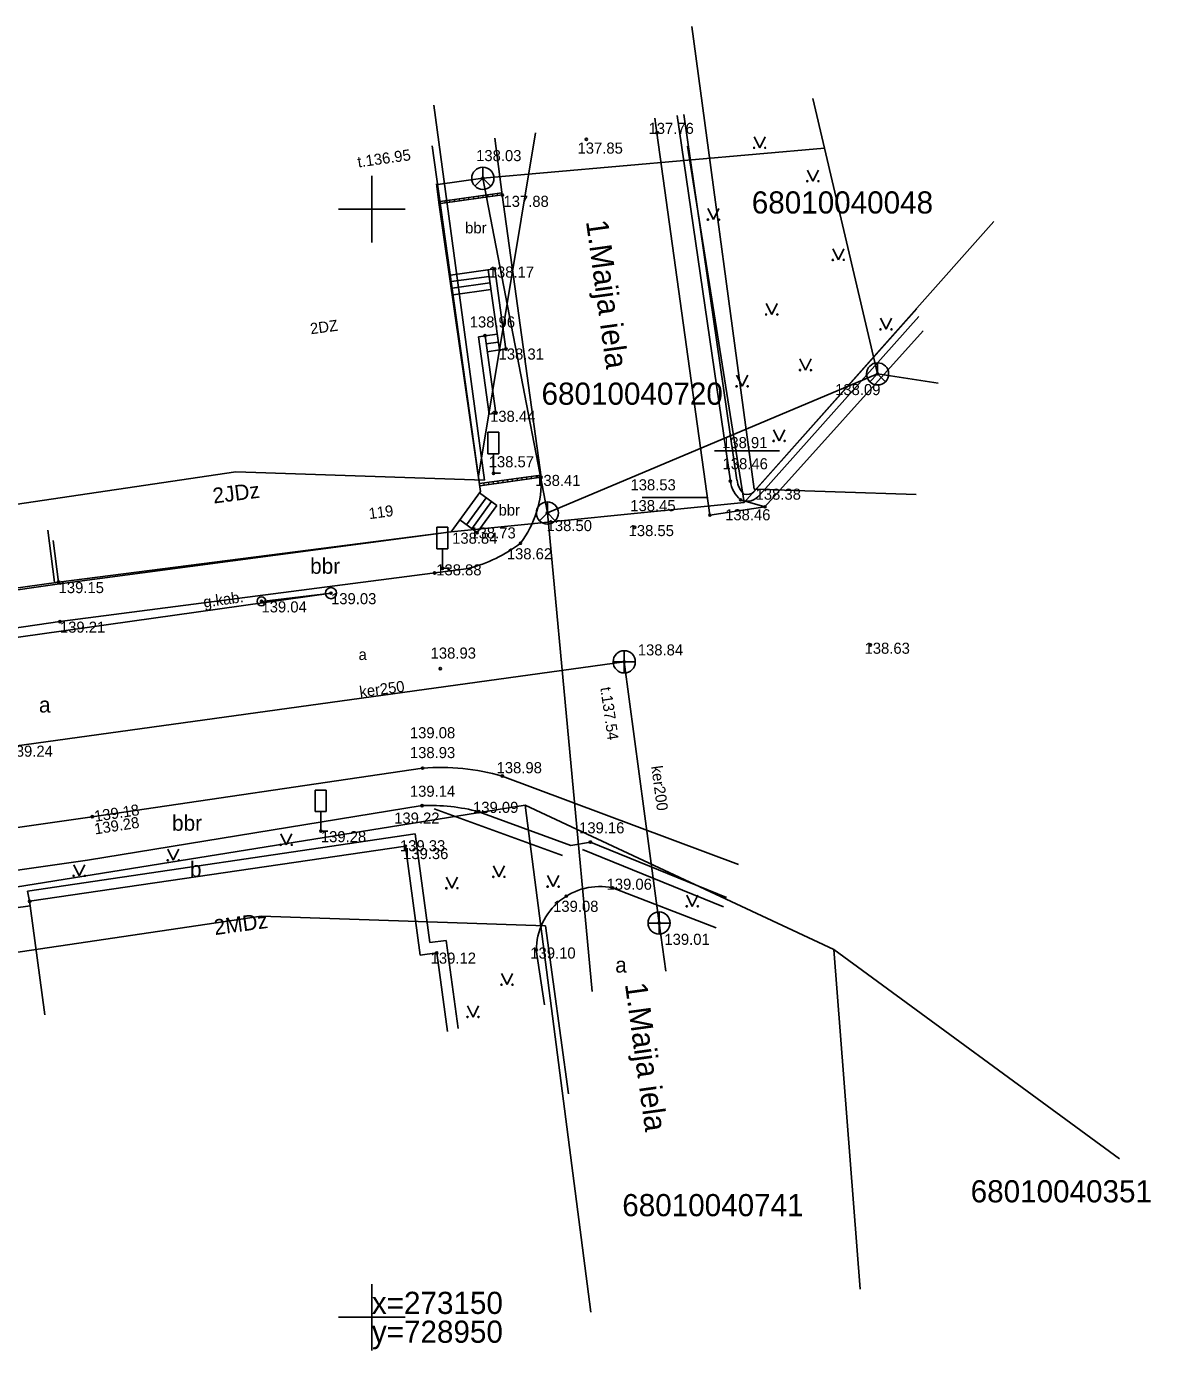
# Model space of a CAD drawing. Extents: x 728785 to 728985, y 273137 to 273208.
# Drawn here: x 728934.4 to 728985.1, y 273148.5 to 273208.2 of the extents above; entities that cross this region are included whole.
import ezdxf

# ---------------------------------------------------------------- set-up
doc = ezdxf.new("R2010")
doc.units = 0
for name, color, linetype in [('APGR_SARK_####_####_#', 7, 'Continuous'), ('BUVE_BDET_####_####_#', 7, 'Continuous'), ('BUVE_EKAS_####_####_#', 7, 'Continuous'), ('BUVE_EKAS_ADRS_TKST_#', 7, 'Continuous'), ('BUVE_EKAS_RAKS_TKST_#', 7, 'Continuous'), ('CELI_CAPM_####_####_#', 7, 'Continuous'), ('CELI_CMAL_####_####_#', 7, 'Continuous'), ('CELI_CSEG_####_TKST_#', 7, 'Continuous'), ('CELI_ELEM_####_####_#', 7, 'Continuous'), ('CELI_IELA_####_TKST_#', 7, 'Continuous'), ('ELEK_ELEM_####_####_#', 7, 'Continuous'), ('ELEK_STUT_####_####_#', 7, 'Continuous'), ('ELEK_VADV_ZSPR_####_#', 7, 'Continuous'), ('ELEK_VADV_ZSPR_TKST_#', 7, 'Continuous'), ('GEOD_ELEM_####_####_#', 7, 'Continuous'), ('GEOD_KORD_####_TKST_#', 7, 'Continuous'), ('RELJ_AATZ_####_TKST_#', 7, 'Continuous'), ('RELJ_ELEM_####_####_#', 7, 'Continuous'), ('ROBZ_KADS_####_TKST_#', 7, 'Continuous'), ('ROBZ_UZMR_####_####_#', 7, 'Continuous'), ('SAKK_ELEM_####_####_#', 7, 'Continuous'), ('SAKK_ELEM_####_TKST_#', 7, 'Continuous'), ('SAKK_KKAN_####_####_#', 7, 'Continuous'), ('SAKT_VADV_PKAB_####_#', 7, 'Continuous'), ('SKAN_ELEM_####_####_#', 7, 'Continuous'), ('SKAN_ELEM_PAST_TKST_#', 7, 'Continuous'), ('SKAN_VADP_PAST_####_#', 7, 'Continuous'), ('SKAN_VADP_PAST_TKST_#', 7, 'Continuous'), ('TERT_ELEM_####_####_#', 7, 'Continuous'), ('TERT_KRND_####_####_#', 7, 'Continuous')]:
    doc.layers.add(name, color=color, linetype=linetype)

msp = doc.modelspace()

# ---------------------------------------------------------------- linework, layer by layer
at = {"layer": 'APGR_SARK_####_####_#'}
for points in [[(728964.432, 273208.242), (728967.247, 273187.368)], [(728952.803, 273204.686), (728955.084, 273187.77)], [(728955.084, 273187.77), (728943.86, 273188.14), (728816.642, 273169.324)], [(728974.565, 273187.126), (728967.247, 273187.368)], [(728957.827, 273167.668), (728945.002, 273168.092), (728819.408, 273149.515)], [(728957.827, 273167.668), (728958.876, 273160.079)]]:
    msp.add_lwpolyline(points, dxfattribs=at)
at = {"layer": 'BUVE_BDET_####_####_#'}
for p, q in [((728955.87, 273200.739), (728953.077, 273200.348)), ((728955.884, 273200.64), (728953.091, 273200.249)), ((728954.581, 273200.559), (728954.595, 273200.46)), ((728954.796, 273200.589), (728954.809, 273200.49)), ((728955.011, 273200.619), (728955.024, 273200.52)), ((728955.225, 273200.649), (728955.239, 273200.55)), ((728955.44, 273200.679), (728955.454, 273200.58)), ((728955.655, 273200.709), (728955.669, 273200.61)), ((728953.291, 273200.378), (728953.305, 273200.279)), ((728953.506, 273200.408), (728953.52, 273200.309)), ((728953.721, 273200.438), (728953.735, 273200.339)), ((728953.936, 273200.468), (728953.95, 273200.369)), ((728954.151, 273200.499), (728954.165, 273200.399)), ((728954.366, 273200.529), (728954.38, 273200.43)), ((728955.543, 273197.305), (728953.542, 273197.025)), ((728955.752, 273193.645), (728955.246, 273197.263)), ((728956.049, 273193.687), (728955.543, 273197.305)), ((728955.288, 273196.966), (728953.583, 273196.728)), ((728955.329, 273196.669), (728953.625, 273196.431)), ((728955.371, 273196.372), (728953.666, 273196.134)), ((728967.233, 273187.247), (728974.588, 273195.499)), ((728967.507, 273187.103), (728974.686, 273195.157)), ((728954.808, 273194.246), (728955.105, 273194.288)), ((728954.808, 273194.246), (728955.296, 273190.754)), ((728955.105, 273194.288), (728955.651, 273194.364)), ((728955.105, 273194.288), (728955.594, 273190.796)), ((728955.702, 273194.005), (728955.155, 273193.928)), ((728955.752, 273193.645), (728955.206, 273193.569)), ((728955.752, 273193.645), (728956.049, 273193.687)), ((728955.594, 273190.796), (728955.296, 273190.754)), ((728957.625, 273188.001), (728954.858, 273187.614)), ((728957.639, 273187.902), (728954.872, 273187.515)), ((728955.046, 273187.64), (728955.06, 273187.541)), ((728955.261, 273187.67), (728955.275, 273187.571)), ((728955.476, 273187.7), (728955.49, 273187.601)), ((728955.691, 273187.73), (728955.705, 273187.631)), ((728955.906, 273187.761), (728955.92, 273187.661)), ((728956.121, 273187.791), (728956.135, 273187.692)), ((728956.336, 273187.821), (728956.35, 273187.722)), ((728956.551, 273187.851), (728956.564, 273187.752)), ((728956.766, 273187.881), (728956.779, 273187.782)), ((728956.98, 273187.911), (728956.994, 273187.812)), ((728957.195, 273187.941), (728957.209, 273187.842)), ((728957.41, 273187.971), (728957.424, 273187.872)), ((728955.162, 273186.98), (728954.268, 273185.76)), ((728955.646, 273186.625), (728954.86, 273187.201)), ((728955.404, 273186.802), (728954.51, 273185.582)), ((728955.646, 273186.625), (728954.752, 273185.405)), ((728954.752, 273185.405), (728953.965, 273185.981))]:
    msp.add_line(p, q, dxfattribs=at)
for points in [[(728963.779, 273204.229), (728966.178, 273187.727)], [(728964.077, 273204.266), (728966.475, 273187.77)]]:
    msp.add_lwpolyline(points, dxfattribs=at)
for centre, radius, start, end in [((728967.512, 273187.902), 1.345, 187.48945, 229.32211), ((728967.512, 273187.902), 1.045, 187.48945, 226.5951), ((728966.926, 273187.564), 0.742, 246.89324, 321.54999), ((728966.926, 273187.564), 0.442, 252.54509, 314.06019)]:
    msp.add_arc(centre, radius, start, end, dxfattribs=at)
at = {"layer": 'BUVE_EKAS_####_####_#'}
for p, q in [((728954.907, 273187.266), (728952.725, 273202.86)), ((728953.573, 273185.446), (728954.907, 273187.266)), ((728935.865, 273183.174), (728935.613, 273185.044)), ((728935.865, 273183.174), (728953.573, 273185.446)), ((728934.555, 273168.77), (728951.518, 273171.257)), ((728951.518, 273171.257), (728952.182, 273166.341)), ((728934.577, 273168.568), (728904.348, 273164.427)), ((728934.577, 273168.568), (728934.555, 273168.77)), ((728934.577, 273168.568), (728935.241, 273163.652)), ((728952.182, 273166.341), (728952.929, 273166.441)), ((728952.929, 273166.441), (728953.408, 273162.896))]:
    msp.add_line(p, q, dxfattribs=at)
at = {"layer": 'CELI_CAPM_####_####_#'}
for p, q in [((728954.356, 273183.788), (728935.924, 273181.389)), ((728960.861, 273169.379), (728965.534, 273167.577))]:
    msp.add_line(p, q, dxfattribs=at)
for points in [[(728962.772, 273204.104), (728962.864, 273203.444), (728965.252, 273186.192)], [(728955.544, 273203.209), (728955.884, 273200.64)], [(728957.639, 273187.902), (728955.884, 273200.64)], [(728857.186, 273170.288), (728877.231, 273172.928), (728915.793, 273178.486), (728920.739, 273179.175), (728935.924, 273181.389)], [(728855.438, 273160.854), (728872.218, 273163.259), (728890.623, 273165.918), (728899.975, 273167.245), (728913.935, 273169.231), (728937.385, 273172.585), (728952.292, 273174.776)], [(728955.886, 273174.422), (728966.54, 273170.436)], [(728957.419, 273166.578), (728957.786, 273164.105)]]:
    msp.add_lwpolyline(points, dxfattribs=at)
for centre, radius, start, end in [((728953.078, 273187.699), 4.566, 322.60338, 2.54831), ((728952.736, 273190.127), 6.542, 284.34371, 307.35294), ((728953.084, 273164.396), 10.41, 74.3859, 94.36341), ((728960.291, 273166.564), 2.872, 78.54555, 180)]:
    msp.add_arc(centre, radius, start, end, dxfattribs=at)
at = {"layer": 'CELI_CMAL_####_####_#'}
for p, q in [((728967.738, 273186.566), (728966.635, 273186.882)), ((728934.468, 273169.221), (728951.947, 273171.819)), ((728951.947, 273171.819), (728952.61, 273166.903)), ((728952.61, 273166.903), (728953.358, 273167.004)), ((728953.358, 273167.004), (728953.894, 273163.03))]:
    msp.add_line(p, q, dxfattribs=at)
for points in [[(728967.738, 273186.566), (728974.873, 273194.504)], [(728965.252, 273186.192), (728967.738, 273186.566)], [(728935.675, 273183.171), (728935.38, 273185.516)], [(728935.865, 273183.174), (728921.973, 273181.228), (728909.161, 273179.346)], [(728952.265, 273173.086), (728937.162, 273170.62), (728913.708, 273167.266), (728899.747, 273165.28), (728895.607, 273164.692)], [(728954.828, 273172.809), (728958.98, 273171.292), (728959.86, 273171.44), (728966.002, 273168.939)], [(728934.468, 273169.221), (728934.555, 273168.77)]]:
    msp.add_lwpolyline(points, dxfattribs=at)
msp.add_arc((728952.64, 273164.557), 8.537, 75.14778, 92.51546, dxfattribs=at)
at = {"layer": 'CELI_ELEM_####_####_#'}
for p, q in [((728955.736, 273189.93), (728955.236, 273189.93)), ((728955.236, 273188.961), (728955.236, 273189.93)), ((728955.736, 273188.961), (728955.736, 273189.93)), ((728955.736, 273188.961), (728955.236, 273188.961)), ((728955.49, 273188.961), (728955.49, 273188.083)), ((728955.49, 273188.083), (728955.805, 273188.083)), ((728953.43, 273185.643), (728952.93, 273185.643)), ((728952.93, 273184.674), (728952.93, 273185.643)), ((728953.43, 273184.674), (728953.43, 273185.643)), ((728953.43, 273184.674), (728952.93, 273184.674)), ((728953.184, 273184.674), (728953.184, 273183.796)), ((728953.184, 273183.796), (728953.499, 273183.796)), ((728947.944, 273173.783), (728947.444, 273173.783)), ((728947.444, 273172.814), (728947.444, 273173.783)), ((728947.944, 273172.814), (728947.944, 273173.783)), ((728947.944, 273172.814), (728947.444, 273172.814)), ((728947.698, 273172.814), (728947.698, 273171.936)), ((728947.698, 273171.936), (728948.013, 273171.936))]:
    msp.add_line(p, q, dxfattribs=at)
at = {"layer": 'ELEK_ELEM_####_####_#'}
for centre, radius in [((728948.158, 273182.674), 0.25), ((728945.018, 273182.304), 0.2)]:
    msp.add_circle(centre, radius, dxfattribs=at)
at = {"layer": 'ELEK_STUT_####_####_#'}
msp.add_line((728945.018, 273182.304), (728948.158, 273182.674), dxfattribs=at)
at = {"layer": 'ELEK_VADV_ZSPR_####_#'}
msp.add_line((728911.092, 273177.457), (728948.158, 273182.674), dxfattribs=at)
at = {"layer": 'GEOD_ELEM_####_####_#'}
for p, q in [((728950, 273201.5), (728950, 273200)), ((728948.5, 273200), (728950, 273200)), ((728950, 273200), (728950, 273198.5)), ((728950, 273200), (728951.5, 273200)), ((728950, 273151.5), (728950, 273150)), ((728948.5, 273150), (728950, 273150)), ((728950, 273150), (728950, 273148.5)), ((728950, 273150), (728951.5, 273150))]:
    msp.add_line(p, q, dxfattribs=at)
at = {"layer": 'RELJ_ELEM_####_####_#'}
for p, q in [((728965.467, 273189.094), (728968.4, 273189.094)), ((728962.195, 273186.984), (728965.129, 273186.984))]:
    msp.add_line(p, q, dxfattribs=at)
for centre in [(728959.679, 273203.148), (728962.864, 273203.444), (728955.007, 273201.391), (728955.884, 273200.64), (728955.543, 273197.305), (728955.105, 273194.288), (728956.049, 273193.687), (728972.817, 273192.568), (728955.603, 273190.797), (728955.49, 273188.083), (728957.639, 273187.902), (728966.178, 273187.727), (728966.635, 273186.882), (728957.921, 273186.291), (728965.252, 273186.192), (728967.738, 273186.566), (728961.855, 273185.639), (728954.752, 273185.405), (728956.705, 273184.926), (728953.184, 273183.796), (728952.833, 273183.585), (728935.865, 273183.174), (728948.158, 273182.674), (728945.018, 273182.304), (728935.924, 273181.389), (728972.501, 273180.331), (728953.086, 273179.269), (728961.386, 273179.575), (728952.292, 273174.776), (728955.886, 273174.422), (728952.265, 273173.086), (728937.385, 273172.585), (728954.828, 273172.809), (728947.698, 273171.936), (728951.518, 273171.257), (728959.86, 273171.44), (728958.774, 273169.003), (728960.861, 273169.379), (728934.555, 273168.77), (728962.961, 273167.79), (728957.419, 273166.578), (728952.929, 273166.441)]:
    msp.add_circle(centre, 0.05, dxfattribs=at)
at = {"layer": 'ROBZ_UZMR_####_####_#'}
for p, q in [((728964.242, 273202.838), (728966.793, 273186.771)), ((728953.025, 273200.307), (728952.913, 273201.149)), ((728954.907, 273187.266), (728953.025, 273200.307)), ((728966.793, 273186.771), (728978.057, 273199.438)), ((728953.573, 273185.446), (728954.907, 273187.266)), ((728953.573, 273185.446), (728966.793, 273186.771)), ((728935.806, 273183.076), (728953.573, 273185.446)), ((728909.118, 273179.219), (728935.806, 273183.076)), ((728956.923, 273173.1), (728912.452, 273165.969)), ((728959.876, 273150.232), (728956.923, 273173.1)), ((728956.923, 273173.1), (728970.845, 273166.598)), ((728970.845, 273166.598), (728972.039, 273151.262)), ((728983.732, 273157.149), (728970.845, 273166.598))]:
    msp.add_line(p, q, dxfattribs=at)
at = {"layer": 'SAKK_ELEM_####_####_#'}
for p, q in [((728955.007, 273201.391), (728955.361, 273201.037)), ((728972.817, 273192.568), (728973.171, 273192.214)), ((728957.921, 273186.291), (728958.275, 273185.937))]:
    msp.add_line(p, q, dxfattribs=at)
for points in [[(728955.007, 273201.891), (728955.007, 273201.391), (728954.653, 273201.037)], [(728972.817, 273193.068), (728972.817, 273192.568), (728972.463, 273192.214)], [(728957.921, 273186.791), (728957.921, 273186.291), (728957.567, 273185.937)]]:
    msp.add_lwpolyline(points, dxfattribs=at)
for centre in [(728955.007, 273201.391), (728972.817, 273192.568), (728957.921, 273186.291)]:
    msp.add_circle(centre, 0.5, dxfattribs=at)
at = {"layer": 'SAKK_KKAN_####_####_#'}
for points in [[(728972.817, 273192.568), (728969.892, 273204.986)], [(728955.007, 273201.391), (728970.417, 273202.756)], [(728955.007, 273201.391), (728952.971, 273201.106)], [(728957.921, 273186.291), (728955.007, 273201.391)], [(728957.921, 273186.291), (728972.817, 273192.568)], [(728972.817, 273192.568), (728975.55, 273192.142)], [(728959.941, 273164.7), (728957.921, 273186.291)]]:
    msp.add_lwpolyline(points, dxfattribs=at)
at = {"layer": 'SAKT_VADV_PKAB_####_#'}
msp.add_line((728957.382, 273203.437), (728954.811, 273187.951), dxfattribs=at)
at = {"layer": 'SKAN_ELEM_####_####_#'}
for p, q in [((728961.386, 273179.075), (728961.386, 273180.075)), ((728960.886, 273179.575), (728961.886, 273179.575)), ((728962.461, 273167.79), (728963.461, 273167.79)), ((728962.961, 273167.29), (728962.961, 273168.29))]:
    msp.add_line(p, q, dxfattribs=at)
for centre in [(728961.386, 273179.575), (728962.961, 273167.79)]:
    msp.add_circle(centre, 0.5, dxfattribs=at)
at = {"layer": 'SKAN_VADP_PAST_####_#'}
for points in [[(728858.768, 273165.198), (728904.501, 273171.712), (728961.386, 273179.575)], [(728962.961, 273167.79), (728961.386, 273179.575)], [(728963.266, 273165.617), (728962.961, 273167.79)]]:
    msp.add_lwpolyline(points, dxfattribs=at)
at = {"layer": 'TERT_ELEM_####_####_#'}
for p, q in [((728967.251, 273203.267), (728967.501, 273202.767)), ((728967.501, 273202.767), (728967.751, 273203.267)), ((728969.651, 273201.762), (728969.901, 273201.262)), ((728969.901, 273201.262), (728970.151, 273201.762)), ((728965.163, 273200.028), (728965.413, 273199.528)), ((728965.413, 273199.528), (728965.663, 273200.028)), ((728970.799, 273198.211), (728971.049, 273197.711)), ((728971.049, 273197.711), (728971.299, 273198.211)), ((728967.793, 273195.746), (728968.043, 273195.246)), ((728968.043, 273195.246), (728968.293, 273195.746)), ((728972.949, 273195.077), (728973.199, 273194.577)), ((728973.199, 273194.577), (728973.449, 273195.077)), ((728969.317, 273193.239), (728969.567, 273192.739)), ((728969.567, 273192.739), (728969.817, 273193.239)), ((728966.458, 273192.507), (728966.708, 273192.007)), ((728966.708, 273192.007), (728966.958, 273192.507)), ((728968.127, 273190.042), (728968.377, 273189.542)), ((728968.377, 273189.542), (728968.627, 273190.042)), ((728945.889, 273171.82), (728946.139, 273171.32)), ((728946.139, 273171.32), (728946.389, 273171.82)), ((728940.79, 273171.118), (728941.04, 273170.618)), ((728941.04, 273170.618), (728941.29, 273171.118)), ((728936.547, 273170.417), (728936.797, 273169.917)), ((728936.797, 273169.917), (728937.047, 273170.417)), ((728955.482, 273170.371), (728955.732, 273169.871)), ((728955.732, 273169.871), (728955.982, 273170.371)), ((728953.364, 273169.86), (728953.614, 273169.36)), ((728953.614, 273169.36), (728953.864, 273169.86)), ((728957.93, 273169.933), (728958.18, 273169.433)), ((728958.18, 273169.433), (728958.43, 273169.933)), ((728964.209, 273169.041), (728964.459, 273168.541)), ((728964.459, 273168.541), (728964.709, 273169.041)), ((728955.848, 273165.509), (728956.098, 273165.009)), ((728956.098, 273165.009), (728956.348, 273165.509)), ((728954.314, 273164.046), (728954.564, 273163.546)), ((728954.564, 273163.546), (728954.814, 273164.046))]:
    msp.add_line(p, q, dxfattribs=at)
for centre, radius in [((728967.25, 273202.766), 0.028), ((728967.75, 273202.766), 0.0263), ((728969.651, 273201.262), 0.028), ((728970.151, 273201.262), 0.0263), ((728965.163, 273199.528), 0.028), ((728965.663, 273199.528), 0.0263), ((728970.799, 273197.71), 0.028), ((728971.299, 273197.71), 0.0263), ((728967.793, 273195.245), 0.028), ((728968.293, 273195.245), 0.0263), ((728972.949, 273194.577), 0.028), ((728973.449, 273194.577), 0.0263), ((728969.317, 273192.738), 0.028), ((728969.817, 273192.738), 0.0263), ((728966.457, 273192.007), 0.028), ((728966.957, 273192.007), 0.0263), ((728968.127, 273189.542), 0.028), ((728968.627, 273189.542), 0.0263), ((728945.889, 273171.319), 0.028), ((728946.389, 273171.319), 0.0263), ((728940.79, 273170.618), 0.028), ((728941.29, 273170.618), 0.0263), ((728936.547, 273169.917), 0.028), ((728937.047, 273169.917), 0.0263), ((728955.482, 273169.871), 0.028), ((728955.982, 273169.871), 0.0263), ((728953.364, 273169.359), 0.028), ((728953.864, 273169.359), 0.0263), ((728957.929, 273169.432), 0.028), ((728958.429, 273169.432), 0.0263), ((728964.208, 273168.541), 0.028), ((728964.708, 273168.541), 0.0263), ((728955.847, 273165.008), 0.028), ((728956.347, 273165.008), 0.0263), ((728954.313, 273163.546), 0.028), ((728954.813, 273163.546), 0.0263)]:
    msp.add_circle(centre, radius, dxfattribs=at)
at = {"layer": 'TERT_KRND_####_####_#'}
for points in [[(728958.6, 273170.831), (728952.805, 273172.948)], [(728959.5, 273171.111), (728965.859, 273168.522)]]:
    msp.add_lwpolyline(points, dxfattribs=at)

# ---------------------------------------------------------------- texts
at = {"layer": 'BUVE_EKAS_ADRS_TKST_#'}
msp.add_text('119', height=0.5, rotation=7.59802, dxfattribs=at).set_placement((728949.89, 273186.011))
at = {"layer": 'BUVE_EKAS_RAKS_TKST_#'}
for s, height, rotation, p in [('2DZ', 0.5, 7.59802, (728947.248, 273194.353)), ('2JDz', 0.7, 7.31131, (728942.864, 273186.715)), ('2MDz', 0.7, 7.75257, (728942.921, 273167.243))]:
    msp.add_text(s, height=height, rotation=rotation, dxfattribs=at).set_placement(p)
at = {"layer": 'CELI_CSEG_####_TKST_#'}
for s, height, p in [('bbr', 0.5, (728954.209, 273198.906)), ('bbr', 0.5, (728955.718, 273186.175)), ('bbr', 0.7, (728947.216, 273183.546)), ('a', 0.5, (728949.4, 273179.656)), ('a', 0.7, (728934.979, 273177.287)), ('bbr', 0.7, (728940.985, 273171.951)), ('b', 0.7, (728941.793, 273169.865)), ('a', 0.7, (728960.981, 273165.551))]:
    msp.add_text(s, height=height, dxfattribs=at).set_placement(p)
at = {"layer": 'CELI_IELA_####_TKST_#'}
for p in [(728959.657, 273199.45), (728961.416, 273165.038)]:
    msp.add_text('1.Maija iela', height=1, rotation=277.84464, dxfattribs=at).set_placement(p)
at = {"layer": 'ELEK_VADV_ZSPR_TKST_#'}
msp.add_text('g.kab.', height=0.5, rotation=8.01169, dxfattribs=at).set_placement((728942.43, 273182.019))
at = {"layer": 'GEOD_KORD_####_TKST_#'}
for s, p in [('x=273150', (728950, 273150.15)), ('y=728950', (728950, 273148.85))]:
    msp.add_text(s, height=1, dxfattribs=at).set_placement(p)
at = {"layer": 'RELJ_AATZ_####_TKST_#'}
for s, p in [(' 137.76', (728962.297, 273203.395)), (' 137.85', (728959.094, 273202.505)), (' 137.88', (728955.752, 273200.102)), (' 138.17', (728955.087, 273196.912)), (' 138.96', (728954.23, 273194.66)), (' 138.31', (728955.532, 273193.213)), (' 138.44', (728955.147, 273190.404)), (' 138.91', (728965.618, 273189.216)), (' 138.57', (728955.086, 273188.353)), (' 138.46', (728965.638, 273188.261)), (' 138.41', (728957.183, 273187.509)), (' 138.53', (728961.483, 273187.312)), (' 138.45', (728961.474, 273186.372)), (' 138.38', (728967.129, 273186.889)), (' 138.46', (728965.754, 273185.96)), (' 138.73', (728954.259, 273185.142)), (' 138.55', (728961.399, 273185.246)), ('138.84', (728953.621, 273184.903)), (' 138.62', (728955.903, 273184.199)), ('138.88', (728952.904, 273183.475)), ('139.15', (728935.865, 273182.674)), ('139.03', (728948.158, 273182.174)), ('139.04', (728945.018, 273181.804)), ('139.21', (728935.924, 273180.889)), (' 138.63', (728972.045, 273179.938)), (' 138.93', (728952.466, 273179.72)), (' 139.08', (728951.53, 273176.125)), ('139.24', (728933.561, 273175.293)), (' 138.93', (728951.53, 273175.229)), (' 138.98', (728955.442, 273174.548)), (' 139.14', (728951.529, 273173.486)), (' 139.09', (728954.379, 273172.758)), ('139.22', (728951.007, 273172.275)), ('139.28', (728947.698, 273171.436)), (' 139.16', (728959.165, 273171.835)), (' 139.33', (728951.082, 273171.026)), ('139.36', (728951.406, 273170.673)), (' 139.06', (728960.405, 273169.291)), (' 139.08', (728957.992, 273168.293)), (' 139.10', (728956.963, 273166.185)), (' 139.12', (728952.467, 273165.955))]:
    msp.add_text(s, height=0.5, dxfattribs=at).set_placement(p)
for s, p in [('139.18', (728937.515, 273172.353)), ('139.28', (728937.515, 273171.783))]:
    msp.add_text(s, height=0.5, rotation=8.72824, dxfattribs=at).set_placement(p)
at = {"layer": 'ROBZ_KADS_####_TKST_#'}
for s, p in [('68010040048', (728967.142, 273199.803)), ('68010040720', (728957.656, 273191.174)), ('68010040351', (728977.019, 273155.185)), ('68010040741', (728961.299, 273154.56))]:
    msp.add_text(s, height=1, dxfattribs=at).set_placement(p)
at = {"layer": 'SAKK_ELEM_####_TKST_#'}
for s, p in [(' 138.03', (728954.518, 273202.166)), (' 138.09', (728970.717, 273191.609)), (' 138.50', (728957.7, 273185.472))]:
    msp.add_text(s, height=0.5, dxfattribs=at).set_placement(p)
at = {"layer": 'SKAN_ELEM_PAST_TKST_#'}
for s, p in [(' 138.84', (728961.813, 273179.863)), (' 139.01', (728963.013, 273166.804))]:
    msp.add_text(s, height=0.5, dxfattribs=at).set_placement(p)
at = {"layer": 'SKAN_VADP_PAST_TKST_#'}
for s, rotation, p in [('t.136.95', 7.9642, (728949.388, 273201.878)), ('ker250', 7.40233, (728949.472, 273177.969)), ('t.137.54', 278.12419, (728960.305, 273178.403)), ('ker200', 277.61216, (728962.604, 273174.855))]:
    msp.add_text(s, height=0.5, rotation=rotation, dxfattribs=at).set_placement(p)

doc.saveas('drawing.dxf')
